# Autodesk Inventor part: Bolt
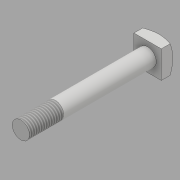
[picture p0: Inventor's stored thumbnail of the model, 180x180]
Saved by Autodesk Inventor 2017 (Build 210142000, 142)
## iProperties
Created: 2016-05
Part Number: Bolt
Material: Generic
Document SubType Name: Modeling
Designer: CADCIM
Density: 1 g/cm^3
Appearance: Default
Author: CADCIM
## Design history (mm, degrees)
sketch "Sketch1"
  geometry: L1 (9.5, 9.5)-(-9.5, 9.5); L2 (-9.5, 9.5)-(-9.5, -9.5); L3 (-9.5, -9.5)-(9.5, -9.5); L4 (9.5, -9.5)-(9.5, 9.5); L5 (0, 0)-(0, 14.108); L6 (0, 0)-(-17.802, 0)
  constraints: 12 end point, 2 horizontal, 2 parallel, 2 perpendicular, 1 vertical, 2 other
  dimensions: "d0" = 19 distance of L3.end L1.start
extrude "Extrusion1" new body sketch "Sketch1" distance "d1" = 8; taper "d2" = 0 deg
sketch "Sketch2"
  geometry: C1 r 6 at (0, 0); 1 further point
  constraints: 1 centre point, 1 coincident
  dimensions: "d3" = 12 diameter of C1
extrude "Extrusion2" join sketch "Sketch2" distance "d4" = 96; taper "d5" = 0 deg
sketch "Sketch3"
  geometry: L1 (9.5, 9.5)-(-9.5, 9.5) reference; C1 r 9.5 at (0, 0); 1 further point
  constraints: 1 centre point, 1 coincident, 1 tangent
extrude "Extrusion3" sketch "Sketch3" distance "d6" = 96; taper "d7" = 65 deg
thread "Thread1" dims "d8" = 24, "d9" = 0
body "Solid1"
